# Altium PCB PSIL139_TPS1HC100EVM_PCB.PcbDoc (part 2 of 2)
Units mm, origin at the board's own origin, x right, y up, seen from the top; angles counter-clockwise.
Board outline 106.25 x 70 mm, 4 copper layers (Top Layer, Power, Ground, Bottom Layer), stack 1.565 mm thick; 66 components, 26 nets, 179 pads, 130 vias.
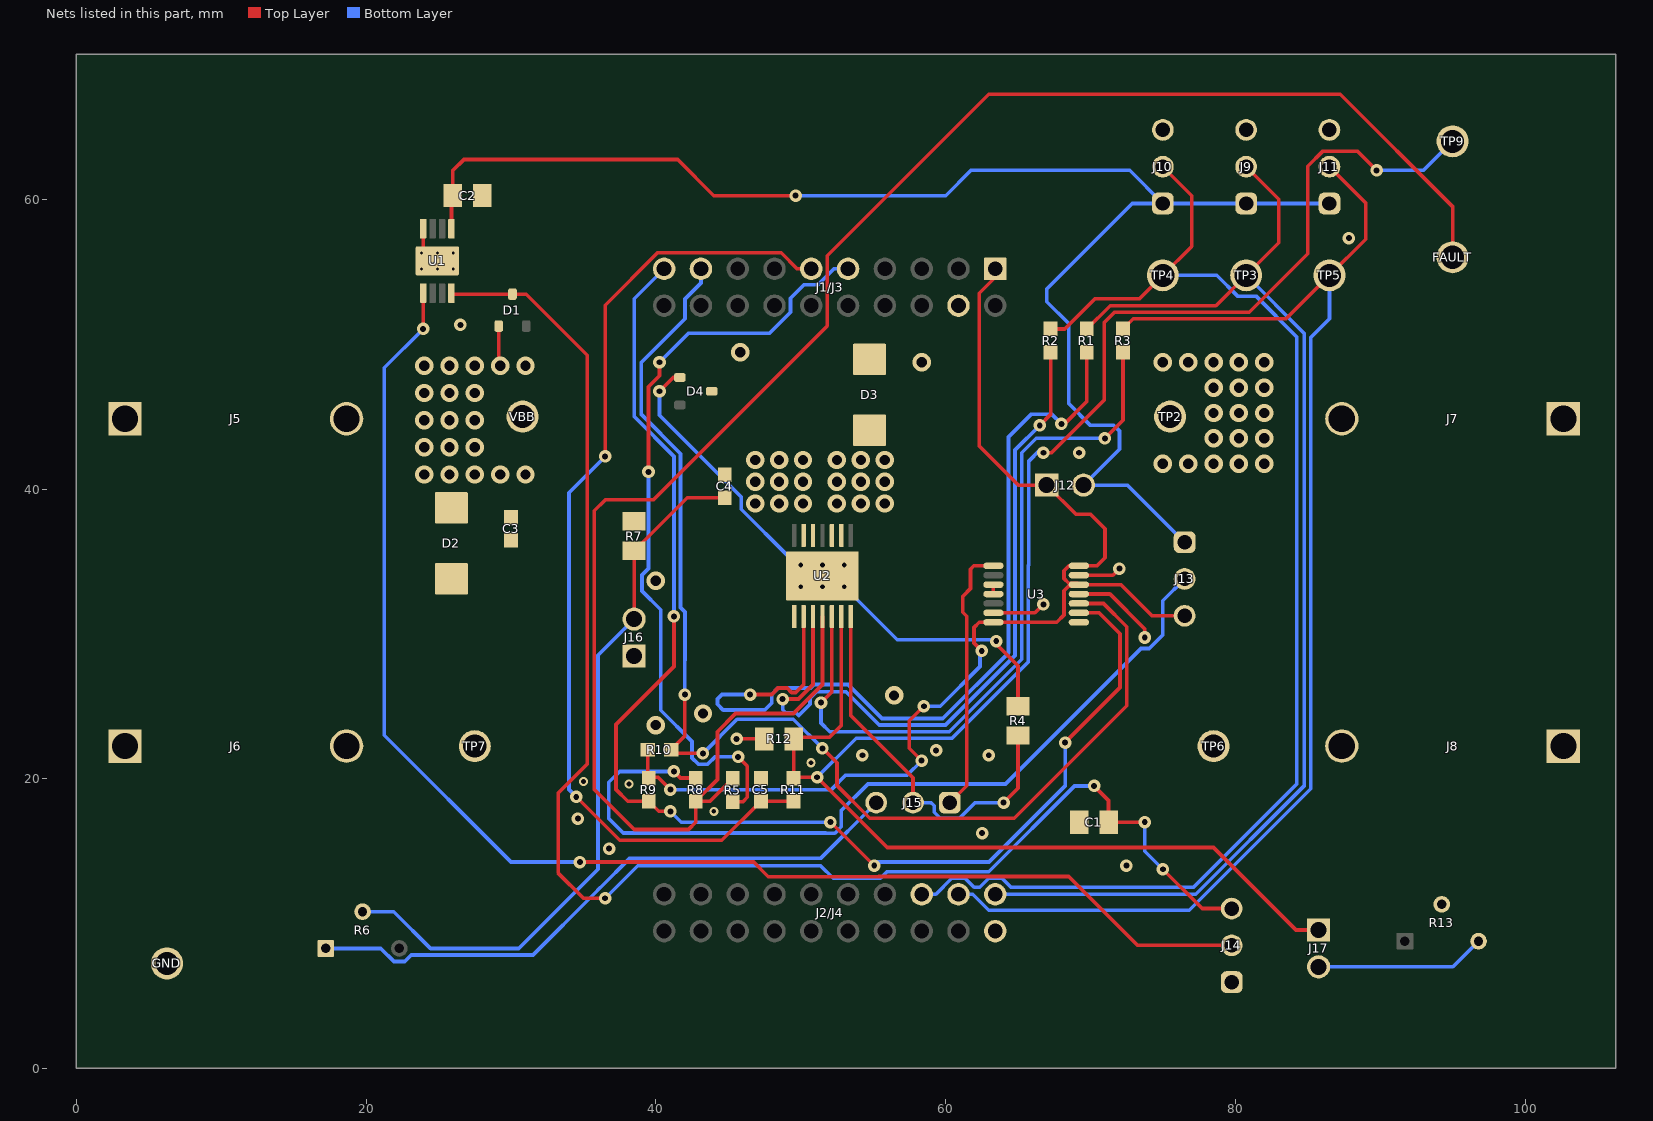
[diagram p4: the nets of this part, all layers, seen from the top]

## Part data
C1: library part CMP-0007980-2, "CAP, CERM, 1 uF, 100 V, +/- 10%, X7S, AEC-Q200 Grade 1, 0805", Cap_Case=0805, Manufacturer=TDK, Supplier Part Number 1=445-6974-1-ND, TempCo=X7S, Tolerance_%=10%, Value1="0.008255 ohm", Value2=100V, ValueDisplayed=1uF
C2: library part CMP-0007977-1, "CAP, CERM, 2.2 uF, 50 V, +/- 10%, X7R, AEC-Q200 Grade 1, 0805", Cap_Case=0805, Manufacturer=TDK, Supplier Part Number 1=445-174216-1-ND, TempCo=X7R, Tolerance_%=10%, Value1="0.003288 ohm", Value2=50V, ValueDisplayed=2.2uF
C3: library part CMP-0007103-2, "CAP, CERM, 0.22 uF, 25 V, +/- 10%, X8R, AEC-Q200 Grade 0, 0603", Cap_Case=0603, Manufacturer=TDK, Supplier Part Number 1=445-12597-1-ND, TempCo=X8R, Tolerance_%=10%, Value1=Unknown, Value2=25V, ValueDisplayed=0.22uF
C4: library part CMP-0007090-1, "CAP, CERM, 0.1 uF, 25 V, +/- 10%, X8R, AEC-Q200 Grade 0, 0603", Cap_Case=0603, Manufacturer=TDK, Supplier Part Number 1=445-5885-1-ND, TempCo=X8R, Tolerance_%=10%, Value1=Unknown, Value2=25V, ValueDisplayed=0.1uF
C5: library part CMP-0007130-1, "CAP, CERM, 100 pF, 100 V, +/- 5%, C0G/NP0, AEC-Q200 Grade 1, 0603", Cap_Case=0603, Manufacturer=MuRata, Supplier Part Number 1=490-4771-1-ND, TempCo=C0G/NP0, Tolerance_%=5%, Value1=Unknown, Value2=100V, ValueDisplayed=100pF
D1 D4: library part CMP-0076901-1, "Diode, Switching, 200 V, 0.2 A, SOT-23", Manufacturer="Diodes Inc.", Supplier Part Number 1=BAS21-FDICT-ND, Value1=0.2A, Value2=1.25V
D2 D3: library part CMP-0086728-1, "Diode TVS Single Bi-Dir 36V 600W 2-Pin SMB", Manufacturer=Littelfuse
FAULT TP3 TP4 TP5 TP9: library part CMP-0055158-1, "Test Point, Multipurpose, Green, TH", Color=Green, Manufacturer=Keystone, Supplier Part Number 1=36-5126-ND
GND TP6 TP7: library part CMP-0055148-1, "Test Point, Multipurpose, Black, TH", Color=Black, Manufacturer=Keystone, Supplier Part Number 1=36-5011-ND
J1/J3: library part CMP-0003837-4, "Receptacle, 2.54mm, 10x2, Tin, TH", Alternate Manufacturer="Major League Electronics", Alternate PartNumber=CRD-081413-A-G, Manufacturer=Samtec, Supplier Part Number 1=SAM1204-10-ND
J2/J4: library part CMP-0078266-2, "Receptacle, 2.54mm, 10x2, Tin, TH", Alternate Manufacturer="Major League Electronics", Alternate PartNumber=CRD-081413-A-G, Manufacturer=Samtec, Supplier Part Number 1=SAM1204-10-ND
J5 J7: library part CMP-0055393-2, "Standard Banana Jack, insulated, 10A, red", Manufacturer="DEM Manufacturing", Supplier Part Number 1=30M0087
J6 J8: library part CMP-0055389-3, "Standard Banana Jack, insulated, 10A, black", Manufacturer="DEM Manufacturing", Supplier Part Number 1=45M6896
J9 J10 J11 J13 J14 J15: library part CMP-0075356-1, "Header, 2.54mm, 3x1, Gold, TH", Color=Black, Current_A=2A, Manufacturer=3M, Supplier Part Number 1=961103-6804-AR-ND
J12 J16 J17: library part CMP-0075197-1, "Header, 2.54mm, 2x1, TH", Color=Black, Current_A=2A, Manufacturer=3M, Supplier Part Number 1=3M9447-ND, Voltage_V=1kV
Logo1: library part CMP-0074844-1
Logo2: library part CMP-0074838-1, "Texas Instrument Corporate Signature"
Logo3: library part CMP-0074847-1, "FCC_disclaimer"
Logo4: library part CMP-0074769-1
R1 R2 R3 R5 R11: library part CMP-0022458-4, "RES, 4.99 k, 1%, 0.1 W, AEC-Q200 Grade 0, 0603", Manufacturer=Vishay-Dale, Power_W=100mW, Supplier Part Number 1=541-4.99KHCT-ND, TempCo="100 ppm/C", Tolerance_%=1%, Value2=0.1W, Value_Code=4k99, ValueDisplayed=4.99k
R4: library part CMP-0021756-3, "RES, 59.0 k, 1%, 0.125 W, AEC-Q200 Grade 0, 0805", Manufacturer=Panasonic, Power_W=125mW, Supplier Part Number 1=P59.0KCCT-ND, TempCo="100 ppm/C", Tolerance_%=1%, Value2=0.125W, Value_Code=59k0, ValueDisplayed=59.0k
R6: library part CMP-0091455-1, "Res Cermet Trimmer 100K Ohm 10% 1/2W 1(Elec)/1(Mech)Turn 5mm (6.71 X 7.04 X 14.63mm) Pin Thru-Hole Tube", Digikey Part Number=3362P-1-104TLF-ND, Manufacturer=Bourns, Mouser Part Number=652-3362P-1-104TLF, Operating Temperature Range="-55°C to +125°C", Power_W=0.5W, TempCo=100ppm/°C, Tolerance_%=10%
R7: library part CMP-0020619-3, "RES, 1.0 k, 5%, 0.125 W, AEC-Q200 Grade 0, 0805", Manufacturer=Panasonic, Power_W=125mW, Supplier Part Number 1=P1.0KACT-ND, TempCo="200 ppm/C", Tolerance_%=5%, Value2=0.125W, Value_Code=1k00, ValueDisplayed=1.0k
R8 R9 R10: library part CMP-0086251-1, "RES, 10.0 k, 0.05%, 0.1 W, AEC-Q200 Grade 0, 0603", Manufacturer=Panasonic, Power_W=100mW, TempCo="10 ppm/C", Tolerance_%=0.05%, Value2=0.1W, Value_Code=10k0, ValueDisplayed=10.0k
R12: library part CMP-0021848-2, "RES, 1.00 k, 1%, 0.25 W, 0805", Manufacturer=Panasonic, Power_W=250mW, Supplier Part Number 1=P16058CT-ND, TempCo="100 ppm/C", Tolerance_%=1%, Value2=0.25W, Value_Code=1k00, ValueDisplayed=1.00k
R13: library part CMP-0091381-1, "1 kOhms 0.5W, 1/2W PC Pins Through Hole Trimmer Potentiometer Cermet 1 Turn Top Finger Adjustment", Digikey Part Number=3362P-1-102TLF-ND, Manufacturer=Bourns, Mouser Part Number=652-3362P-1-102TLF, Operating Temperature Range="-55°C to +125°C", Power_W=500mW, TempCo=100ppm/°C, Tolerance_%=10%
SH-J1 SH-J2 SH-J3 SH-J4 SH-J5 SH-J6 SH-J7 SH-J8 SH-J9: library part CMP-0003623-1, "Shunt, 100mil, Gold plated, Black", Alternate Manufacturer=3M, Alternate PartNumber=969102-0000-DA, Manufacturer=Samtec, Supplier Part Number 1=SNT-100-BK-G-ND
TP2 VBB: library part CMP-0055147-1, "Test Point, Multipurpose, Red, TH", Color=Red, Manufacturer=Keystone, Supplier Part Number 1=36-5010-ND
U1: library part CMP-0035936-2, "Single Output LDO, 100 mA, Fixed 3.3 V Output, 3 to 60 V Input, with Enable and Power Good, 8-pin MSOP (DGN), -40 to 125 degC, Green (RoHS & no Sb/Br)", Manufacturer="Texas Instruments", Power Good=TRUE, Rating=Catalog
U2: library part CMP-0091243-1, "100-mO Single-Channel Smart High-Side Power Switch, HTSSOP14", Manufacturer="Texas Instruments", Max Supply Voltage=28V, Min Supply Voltage=2.6V, Nominal Supply Current=3mA, Operating Temperature Range="-40°C to +150°C"
U3: library part CMP-0066591-1, "256-Taps Dual-Channel Digital Potentiometer With I2C Interface and Nonvolatile Memory, PW0014A (TSSOP-14)", Alternate Manufacturer="Texas Instruments"
ZZ1: library part CMP-0077236-1
ZZ2: library part CMP-0077237-1
ZZ3: library part CMP-0077238-1

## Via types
v1: diameter 1.27, hole 0.711, Top Layer to Bottom Layer, tented both sides, 62 vias
v2: diameter 0.864, hole 0.406, Top Layer to Bottom Layer, tented both sides, 52 vias
v3: diameter 0.63, hole 0.33, Top Layer to Bottom Layer, 6 vias
v4: diameter 0.5, hole 0.2, Top Layer to Bottom Layer, tented both sides, 4 vias
v5: diameter 0.63, hole 0.33, Top Layer to Bottom Layer, tented both sides, 4 vias
v6: diameter 0.5, hole 0.2, Top Layer to Bottom Layer, 2 vias

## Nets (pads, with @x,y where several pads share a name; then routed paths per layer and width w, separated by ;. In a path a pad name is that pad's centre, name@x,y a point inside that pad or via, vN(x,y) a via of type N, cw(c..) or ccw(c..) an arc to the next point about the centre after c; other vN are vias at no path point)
3V3LDO: C2.1 J9.1 J10.1 J11.1 J12.2 J13.1 U1.1 | length 104.2
  Top Layer w0.254: U1.1@25.886,57.975 25.886,60.155 C2.1@25.984,60.253 25.984,61.984 26.75,62.75 41.503,62.75 44,60.253 v2(49.651,60.253)
  Bottom Layer w0.254: v2(49.651,60.253) 60.003,60.253 61.75,62 72.71,62 J10.1@75,59.71 ; J13.1@76.5,36.33 72.562,40.268 J12.2@69.52,40.268 72,42.748 72,44 71.608,44.392 70.009,44.392 68.5,45.901 68.5,51.418 66.991,52.927 66.991,53.814 72.887,59.71 J10.1@75,59.71 ; J11.1@86.5,59.71 J9.1@80.75,59.71 J10.1@75,59.71
DIAG_EN_IC: J2/J4.38 J10.2 R2.1 TP4.1 | length 90.4
  Top Layer w0.254: R2.1@67.25,51.05 68.231,51.05 70.316,53.135 73.385,53.135 TP4.1@75,54.75 77,56.75 77,60.25 J10.2@75,62.25
  Bottom Layer w0.254: J2/J4.38@58.35,12.02 59.332,12.02 60.434,13.122 61.346,13.122 61.968,12.5 62.352,12.5 62.974,13.122 63.886,13.122 64.508,12.5 77.108,12.5 84.25,19.642 84.25,50.5 81.432,53.318 80.157,53.318 78.725,54.75 TP4.1@75,54.75
DIGIPOT_IN: J15.1 U3.1 | length 18.6
  Top Layer w0.254: J15.1@60.29,18.35 61.455,19.515 61.455,31.222 61.178,31.499 61.178,32.588 61.716,33.127 61.716,34.464 61.952,34.7 U3.1@63.3,34.7
DIGIPOT_SCL: J1/J3.9 R10.1 U3.10 | length 85.5
  Top Layer w0.254: v2(42,25.814) 42,22.95 R10.1@41.05,22 41.3,21.75 v2(43.25,21.75) ; v2(51.5,22.1) 52.5,21.1 52.5,19.537 54.764,17.273 64.741,17.273 72.5,25.032 72.5,30.5 70.9,32.1 U3.10@69.2,32.1
  Bottom Layer w0.254: v2(42,25.814) 42,28.179 42.009,28.187 42.009,31.514 41.704,31.819 41.704,42.438 39,45.142 39,48.75 42.008,51.758 42.008,53.116 43.11,54.218 J1/J3.9@43.11,55.2 ; v2(43.25,21.75) 45.608,24.108 49.492,24.108 v2(51.5,22.1)
DIGIPOT_SDA: J1/J3.10 R9.1 U3.9 | length 90.6
  Top Layer w0.254: v2(41,17.75) 40.2,17.75 R9.1@39.5,18.45 38.05,18.45 37.25,19.25 37.25,23.75 41.25,27.75 v2(41.25,31.2) ; v2(52.045,17) 52.077,17 v2(55.077,14) ; v2(68.25,22.5) 72.046,26.296 72.046,30 70.596,31.45 U3.9@69.2,31.45
  Bottom Layer w0.254: J1/J3.10@40.57,55.2 38.5,53.13 38.5,45 41.25,42.25 v2(41.25,31.2) ; v2(41,17.75) 41.75,17 v2(52.045,17) ; v2(55.077,14) 55.327,14.25 63,14.25 68.25,19.5 v2(68.25,22.5)
EN_IC: J2/J4.40 J9.2 R1.1 TP3.1 | length 83.2
  Top Layer w0.254: R1.1@69.75,51.05 71.36,52.66 78.66,52.66 TP3.1@80.75,54.75 83,57 83,60 J9.2@80.75,62.25
  Bottom Layer w0.254: J2/J4.40@63.43,12.02 77.27,12.02 84.75,19.5 84.75,50.75 TP3.1@80.75,54.75
FAULT_IC: FAULT.1 R5.1 R8.1 U2.4 | length 131.7
  Top Layer w0.254: R5.1@45.3,20.02 43.731,18.45 R8.1@42.75,18.45 ; U2.4@51.5,31.2 51.5,26.5 49.5,24.5 45.5,24.5 44.25,23.25 44.25,19.95 R8.1@42.75,18.45 ; FAULT.1@95,56 95,59.5 87.25,67.25 62.979,67.25 51.832,56.103 51.832,51.261 39.821,39.25 36.5,39.25 35.75,38.5 35.75,19.25 38.5,16.5 42.25,16.5 42.75,17 R8.1@42.75,18.45
GND: C1.2 C2.2 C3.2 C5.1 D2.2 D3.2 D4.3 GND.1 J1/J3.22 J2/J4.20 J6.1 J6.2 J8.1 J8.2 J9.3 J10.3 J11.3 J14.1 J16.1 R7.1 R12.2 R13.2 TP6.1 TP7.1 U1.4 U1.9@24.911,55.75 U3.6 U3.8 U3.11 U3.13 | length 16.5
  Top Layer w0.254: v4(23.811,56.3) 23.936,56.425 U1.4@23.936,57.975 ; v2(45.567,22.75) R12.2@47.484,22.75 ; U3.6@63.3,31.45 66.164,31.45 v2(66.75,32.036) ; U3.11@69.2,32.75 71.342,32.75 73.75,30.342 v2(73.75,29.75) ; U3.13@69.2,34.05 71.55,34.05 v2(72,34.5)
  other v1: 40,23.704 43.25,24.5 56.444,25.75 40,33.66 58.35,48.75 45.832,49.45
  other v2: 72.484,14 36.769,15.182 62.522,16.25 34.616,17.25 54.26,21.621 62.979,21.621 59.34,21.962 69.216,42.5 26.5,51.328 87.845,57.318
  other v4: 23.811,55.2 26.011,55.2 26.011,56.3
  other v5: 44,17.75 38.142,19.642 35,19.818 50.709,21.1
  other v6: 24.911,55.2 24.911,56.3
IC_GND: C4.2 D4.1 J16.2 R4.1 R6.2 R7.2 U2.1 U2.15 | length 85.6
  Top Layer w0.254: J16.2@38.5,31.02 R7.2@38.5,35.734 42.166,39.4 C4.2@44.75,39.4 ; v2(40.25,46.75) 41.2,47.7 D4.1@41.65,47.7 ; v2(63.5,29.5) 63.5,29.435 63.43,29.365 65,27.795 R4.1@65,25.016
  Bottom Layer w0.254: R6.2@19.75,10.825 21.91,10.825 24.45,8.285 30.535,8.285 36,13.75 36,28.52 J16.2@38.5,31.02 ; v2(40.25,46.75) 40.25,45.092 45.888,39.454 45.888,38.602 49.148,35.342 49.408,35.342 v3(50,34.75) ; v3(53,33.25) 56.663,29.587 63.413,29.587 v2(63.5,29.5)
  other v3: 50,33.25 51.5,33.25 51.5,34.75 53,34.75
LATCH_IC: J2/J4.39 J11.2 R3.1 TP5.1 | length 89.6
  Top Layer w0.254: R3.1@72.25,51.05 72.95,51.75 83.5,51.75 TP5.1@86.5,54.75 89,57.25 89,59.75 J11.2@86.5,62.25
  Bottom Layer w0.254: J2/J4.39@60.89,12.02 61.872,12.02 62.974,10.918 76.818,10.918 85.204,19.304 85.204,50.454 86.5,51.75 TP5.1@86.5,54.75
NetC1_1: C1.1 D1.3 J14.3 U1.8 | length 104.4
  Top Layer w0.254: U1.8@25.886,53.525 25.961,53.45 D1.3@30.1,53.45 31.05,53.45 35.269,49.231 35.269,21.019 33.25,19 33.25,13.5 35,11.75 v2(36.5,11.75) ; v2(70.25,19.5) 71.25,18.5 C1.1@71.25,17 v2(73.75,17) ; v2(75,13.75) 77.71,11.04 J14.3@79.75,11.04
  Bottom Layer w0.254: v2(36.5,11.75) 38.75,14 51.366,14 52.244,13.122 55.5,13.122 55.954,13.576 62.974,13.576 68.898,19.5 v2(70.25,19.5) ; v2(73.75,17) 73.75,15 v2(75,13.75)
NetJ1/J3_1: J1/J3.1 J12.1 J13.3 R9.2 R10.2 U3.7 U3.12 U3.14 | length 82.8
  Top Layer w0.254: R10.2@39.45,22 39.45,20.1 40.15,20.1 v2(41,19.25) ; v2(58.35,21.25) 57.5,22.1 57.5,24 v2(58.5,25) ; v2(62.5,28.828) 61.963,29.365 61.963,30.435 62.328,30.8 U3.7@63.3,30.8 67.673,30.8 68.173,31.3 68.173,32.979 68.496,33.302 69.102,33.302 U3.12@69.2,33.4 ; J1/J3.1@63.43,55.2 63.43,54.621 62.328,53.519 62.328,42.966 65.027,40.268 J12.1@66.98,40.268 68.998,38.25 70,38.25 71,37.25 71,35.25 70.45,34.7 U3.14@69.2,34.7 68.517,34.7 68.173,34.356 68.173,33.821 68.496,33.498 69.102,33.498 U3.12@69.2,33.4 ; J13.3@76.5,31.25 74.25,31.25 72.1,33.4 U3.12@69.2,33.4
  Bottom Layer w0.254: v2(41,19.25) 52.116,19.25 53.116,20.25 57.35,20.25 v2(58.35,21.25) ; v2(58.5,25) 59.631,25 62.381,27.75 62.381,28.709 v2(62.5,28.828)
NetJ1/J3_5: J1/J3.5 R5.2 | length 53.3
  Top Layer w0.254: v2(39.491,41.184) 39.491,47.064 40.25,47.823 v2(40.25,48.748) ; R5.2@45.3,18.42 46.013,18.42 46.31,18.717 46.31,20.871 v2(45.673,21.507)
  Bottom Layer w0.254: v2(39.491,41.184) 39.491,34.512 39.038,34.059 39.038,32.958 40.33,31.665 40.33,24.734 42.491,22.573 42.491,21.436 42.936,20.991 43.564,20.991 44.08,21.507 v2(45.673,21.507) ; v2(40.25,48.748) 42.252,50.75 47.838,50.75 49.292,52.204 49.292,53.172 50.218,54.098 51.186,54.098 52.288,55.2 J1/J3.5@53.27,55.2
NetJ13_2: J13.2 R8.2 | length 58.5
  Top Layer w0.254: v2(41.25,20.5) 41.7,20.05 R8.2@42.75,20.05
  Bottom Layer w0.254: v2(41.25,20.5) 37.5,20.5 36.75,19.75 36.75,17.25 37.75,16.25 51.722,16.25 51.73,16.241 52.359,16.241 52.803,16.686 52.803,17.803 54.642,19.642 64.142,19.642 73.491,28.991 74.064,28.991 75,29.927 75,32.29 J13.2@76.5,33.79
NetJ14_2: J14.2 U1.5 | length 96.2
  Top Layer w0.254: v2(23.936,51.05) U1.5@23.936,53.525 ; v2(34.75,14.25) 46.75,14.25 47.759,13.241 55.391,13.241 55.4,13.25 68.5,13.25 73.25,8.5 J14.2@79.75,8.5
  Bottom Layer w0.254: v2(23.936,51.05) 21.25,48.364 21.25,23 30,14.25 v2(34.75,14.25)
NetJ15_2: J15.2 R4.2 U2.7 | length 27.1
  Top Layer w0.254: U2.7@53.45,31.2 53.45,24.36 57.75,20.06 J15.2@57.75,18.35 ; v2(64,18.35) 65,19.35 R4.2@65,22.984
  Bottom Layer w0.254: J15.2@57.75,18.35 58.99,18.35 59.213,18.127 59.213,17.684 59.624,17.273 60.956,17.273 62.033,18.35 v2(64,18.35)
NetJ15_3: J15.3 R6.1 | length 42.9
  Bottom Layer w0.254: R6.1@17.21,8.285 21.014,8.285 21.916,7.383 22.664,7.383 23.112,7.831 31.513,7.831 35.741,12.059 35.741,12.064 36.186,12.509 36.191,12.509 38.182,14.5 51.36,14.5 J15.3@55.21,18.35
NetJ17_2: J17.2 R13.3 | length 11.8
  Bottom Layer w0.254: J17.2@85.75,7.015 95.02,7.015 R13.3@96.79,8.785
NetR1_2: R1.2 U2.2 | length 61.5
  Top Layer w0.254: v2(46.5,25.814) 47.991,25.814 48.436,26.259 49.064,26.259 49.369,25.954 49.654,25.954 50.2,26.5 U2.2@50.2,31.2 ; v2(68,44.5) 68.108,44.392 69.75,46.034 R1.2@69.75,49.45
  Bottom Layer w0.254: v2(46.5,25.814) 44.56,25.814 44.25,25.505 44.25,25.141 44.641,24.75 47.509,24.75 47.991,25.232 47.991,25.814 48.436,26.259 50.693,26.259 50.934,26.5 53.265,26.5 55.607,24.158 59.812,24.158 64.342,28.688 64.342,43.592 65.901,45.151 67.349,45.151 v2(68,44.5) 68.108,44.392 v2@68.108,44.25
NetR2_2: R2.2 U2.3 | length 50
  Top Layer w0.254: v2(48.75,25.5) 49.85,25.5 50.85,26.5 U2.3@50.85,31.2 ; v2(66.5,44.392) 67.25,45.142 R2.2@67.25,49.45
  Bottom Layer w0.254: v2(48.75,25.5) 48.75,24.763 48.951,24.562 49.68,24.562 49.871,24.371 50.641,25.141 50.641,25.564 51.085,26.009 51.714,26.009 51.723,26 53.123,26 55.419,23.704 60,23.704 64.796,28.5 64.796,42.688 v2(66.5,44.392)
NetR3_2: R3.2 U2.5 | length 50.7
  Top Layer w0.254: v2(51.4,25.25) 52.15,26.001 U2.5@52.15,31.2 ; v2(71,43.5) 72.25,44.75 R3.2@72.25,49.45
  Bottom Layer w0.254: v2(51.4,25.25) 51.4,23.851 52,23.25 60.25,23.25 65.25,28.25 65.25,42.5 66.25,43.5 v2(71,43.5)
NetU3_3: U3.3 U3.4 | length 0.7
  Top Layer w0.254: U3.4@63.3,32.75 U3.3@63.3,33.4
SNS_BP: C5.2 J1/J3.6 R11.1 | length 68.7
  Top Layer w0.254: v2(34.5,18.75) 37.5,15.75 44.55,15.75 C5.2@47.25,18.45 R11.1@49.5,18.45 ; v2(36.5,42.25) 36.5,52.688 40.114,56.302 48.646,56.302 49.748,55.2 J1/J3.6@50.73,55.2
  Bottom Layer w0.254: v2(34.5,18.75) 34,19.25 34,39.75 v2(36.5,42.25)
SNS_IC: J17.1 R11.2 R12.1 TP9.1 U2.6 | length 132.6
  Top Layer w0.254: R11.2@49.5,20.05 R11.2@49.516,20.066 ; U2.6@52.8,31.2 52.8,23.67 51.989,22.859 49.625,22.859 R12.1@49.516,22.75 R11.2@49.516,20.066 ; v2(66.75,42.5) 67.312,42.5 70.95,46.138 70.95,51.496 71.66,52.206 80.956,52.206 85,56.25 85,62.273 86.054,63.327 88.423,63.327 v2(89.75,62) ; J17.1@85.75,9.555 84.195,9.555 78.5,15.25 55.978,15.25 v2(51.128,20.1) 49.55,20.1 R11.2@49.516,20.066
  Bottom Layer w0.254: v2(51.128,20.1) 53.824,22.796 60.438,22.796 65.704,28.062 65.704,34.722 65.75,34.768 65.75,41.938 66.5,42.688 66.562,42.688 v2(66.75,42.5) ; v2(89.75,62) 93,62 TP9.1@95,64
VBB: C3.1 C4.1 D1.1 D2.1 J5.1 J5.2 U2.12 U2.13 VBB.1 | length 2.8
  Top Layer w0.254: D1.1@29.15,51.25 29.15,48.6 v1(29.25,48.5)
  other v1: 46.85,39 48.505,39 50.16,39 46.85,40.5 48.505,40.5 50.16,40.5 24,41 25.75,41 27.5,41 29.25,41 31,41 46.85,42 48.505,42 50.16,42 24,42.875 25.75,42.875 27.5,42.875 24,44.75 25.75,44.75 27.5,44.75 24,46.625 25.75,46.625 27.5,46.625 24,48.5 25.75,48.5 27.5,48.5 31,48.5
VOUT: D3.1 J7.1 J7.2 TP2.1 U2.9 U2.10
  other v1: 52.5,39 54.155,39 55.81,39 52.5,40.5 54.155,40.5 55.81,40.5 75,41.75 76.75,41.75 78.5,41.75 80.25,41.75 82,41.75 52.5,42 54.155,42 55.81,42 78.5,43.5 80.25,43.5 82,43.5 78.5,45.25 80.25,45.25 82,45.25 78.5,47 80.25,47 82,47 75,48.75 76.75,48.75 78.5,48.75 80.25,48.75 82,48.75
pads on no net: D1.2 D4.2 J1/J3.2 J1/J3.3 J1/J3.4 J1/J3.7 J1/J3.8 J1/J3.21 J1/J3.23 J1/J3.24 J1/J3.25 J1/J3.26 J1/J3.27 J1/J3.28 J1/J3.29 J1/J3.30 J2/J4.11 J2/J4.12 J2/J4.13 J2/J4.14 J2/J4.15 J2/J4.16 J2/J4.17 J2/J4.18 J2/J4.19 J2/J4.31 J2/J4.32 J2/J4.33 J2/J4.34 J2/J4.35 J2/J4.36 J2/J4.37 R6.3 R13.1 SH-J1.0 SH-J2.0 SH-J3.0 SH-J4.0 SH-J5.0 SH-J6.0 SH-J7.0 SH-J8.0 SH-J9.0 U1.2 U1.3 U1.6 U1.7 U1.9@24.911,55.75 U2.8 U2.11 U2.14 U3.2 U3.5
copper on no net: | length 1.6
  Top Layer w0.254: v2@61.75,32 62.594,32 62.596,32.002 63.202,32.002 63.3,32.1
  other v2: 62,32

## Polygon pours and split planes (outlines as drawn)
IC_GND on Top Layer "TOP_LAYER_IC_GND_P070" (solid, remove dead copper, pour order 70): 42.99,41 42.948,27.25 60.85,27.25 60.85,41
VBB on Top Layer "TOP_LAYER_VBB_P068" (solid, remove dead copper, pour order 68): 51,36 51,43.5 45.65,43.5 45.65,41.5 44.5,41.5 44.5,40.5 45.75,40.5 45.75,38 49.585,38 50,37.585 50,36
VOUT on Top Layer "TOP_LAYER_VOUT_P069" (solid, remove dead copper, pour order 69): 52,36 53,36 53,37.75 56.75,37.75 56.75,43 55.834,43 55.834,45.25 53.5,45.25 53.5,43.5 51.25,43.5 51.25,38.107 51.976,37.508
GND on Top Layer "TOP_LAYER_GND_P073" (solid, remove dead copper, pour order 73): 0,70 106,70 106.25,69.75 106.25,0 0.25,0 0,-0.25
VBB on Top Layer "TOP_LAYER_VBB_P072" (solid, remove dead copper, pour order 72): 1,49.75 33,49.75 33,37.5 24.25,37.5 22.25,39.75 1.257,40
VOUT on Top Layer "TOP_LAYER_VOUT_P071" (solid, remove dead copper, pour order 71): 105.75,50 73.5,50 73.5,40 105.75,40
VOUT on Power "POWER_VOUT_P075" (solid, remove dead copper, pour order 75): 51.5,69.353 51.5,0.647 51.603,0.75 106,0.75 106,68.75 105.25,69.5
VBB on Power "POWER_VBB_P074" (solid, remove dead copper, pour order 74): 0,69.75 0.25,70 51,70 51,0.25 51.25,0 0,0
GND on Bottom Layer "BOTTOM_LAYER_GND_P078" (solid, remove dead copper, pour order 78): 0.5,69.75 0.25,69.5 0.25,0 105.75,0 106,0.25 105.75,0.5 105.75,69.75
IC_GND on Bottom Layer "BOTTOM_LAYER_IC_GND_P077" (solid, remove dead copper, pour order 77): 42.57,42.5 42.57,27 60.75,27 60.75,42.5
GND on Ground "GROUND_GND_P076" (solid, remove dead copper, pour order 76): 0.25,70 106.25,70 106.25,0.25 0.25,0.25

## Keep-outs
Keep-Out Layer:
  text ".Layer_Name" at 14.656,-21.806 h1.52

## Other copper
Top Layer:
  text ".Layer_Name" at 14.656,-21.806 h1.52
Bottom Layer:
  text ".Layer_Name" at 14.656,-21.806 h1.52

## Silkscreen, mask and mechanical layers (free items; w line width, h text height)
Top Overlay:
  text "DIAG_EN" at 73,67.25 h1.2
  text "EN" at 80.093,67.263 h1.2
  text "LATCH" at 85,67.25 h1.2
  text "PSIL139 A2" at 2,67 h1.85
  text "SNS" at 93.75,67 h1.5
  text "GND" at 70.045,64.5 h1.2
  text "3V3 LDO" at 68,59.25 h1.2
  text "SDA" at 40.57,56.75 h0.6 r45
  text "SCL" at 43.11,56.75 h0.6 r45
  text "SNS" at 50.73,56.75 h0.6 r45
  text "FAULT" at 53.25,56.75 h0.6 r45
  text "VOUT" at 68,45 h2
  text "LDO to BP / Power" at 58.35,39.2 h1.2
  text "LDO" at 78.5,35.931 h1.5
  text "BP" at 78.5,30.5 h1.5
  text "Fault Pull-Up" at 73.5,28 h1.5
  text "(ILIM)" at 64.718,26.669 h1
  text "GND Net / Bypass" at 35,24 h1.2
  text "(SNS)" at 52.643,22.859 h1
  text "GND" at 30.5,21.75 h1.85
  text "GND" at 71.75,21.75 h1.9
  text "DIGI POT" at 60.25,20.114 h1 r45
  text "POT" at 55,20.1 h1 r45
  text "Current Limit / Setting" at 52.964,14 h1
  text "EN" at 52.99,13.561 h0.6 r45
  text "DIAG_EN" at 47.948,13.442 h0.6 r45
  text "LATCH" at 50.488,13.442 h0.7 r45
  text "LDO EN" at 73.25,10.75 h1.2
  text "LDO DIS" at 73.25,5.5 h1.2
  text "TPS1HC100EVM" at 41,3.75 h2.75
  text "SNS Pot  / Enable" at 82.5,2.5 h1
  text "Current Limit" at 15.5,2 h1.85
  text "SNS" at 90.25,2 h1.85
  text ".Layer_Name" at 14.656,-21.806 h1.52
Bottom Overlay:
  text ".Layer_Name" at 14.656,-21.806 h1.52
Top Paste:
  text ".Layer_Name" at 14.656,-21.806 h1.52
Bottom Paste:
  text ".Layer_Name" at 14.656,-21.806 h1.52
Top Solder:
  text ".Layer_Name" at 14.656,-21.806 h1.52
  text ".Layer_Name" at 14.656,-21.806 h1.52
Bottom Solder:
  text ".Layer_Name" at 14.656,-21.806 h1.52
Drill Guide:
  text ".Layer_Name" at 14.656,-21.806 h1.52
M1 Board Outline:
  lines w0.254: -12.5,-0.32 106.25,0 106.25,69.18 ; 0,1.75 0,70 106.25,70
  text ".Layer_Name" at 14.656,-21.806 h1.52
M2 Board Dimensions:
  rectangle: 0,-6.985 3.175,-3.81
  rectangle: 3.175,-10.16 12.7,-6.985
  lines w0.178: 0,-6.985 25.4,-6.985 ; 3.175,-10.16 3.175,-3.81 ; 6.35,-10.16 6.35,-3.81 ; 12.7,-10.16 12.7,-3.81 ; 19.05,-10.16 19.05,-3.81 ; 0,-10.16 25.4,-10.16 25.4,-3.81 0,-3.81 0,-10.16
  text ".Layer_Name" at 14.656,-21.806 h1.52
M3 3D STEP Top:
  text ".Layer_Name" at 14.656,-21.806 h1.52
M4 3D STEP Bottom:
  text ".Layer_Name" at 14.656,-21.806 h1.52
M5 Assembly Top:
  lines w0.254: -7.417,-23.626 160.223,-23.626 ; -7.417,-18.462 160.274,-18.462 ; -7.417,-13.297 -7.417,-28.791 94.31,-28.791 160.274,-28.791 160.274,-13.297 -7.404,-13.297 -7.404,-28.791 32.614,-28.791 ; 55.194,-28.791 55.194,-13.297 ; 87.376,-18.462 87.376,-13.297 ; 108.712,-18.462 108.712,-13.297 ; 124.511,-28.956 124.511,-23.804
  text "COMPONENTS MARKED 'DNP' SHOULD NOT BE POPULATED." at 29.299,-8.09 h1.52
  text "ASSEMBLY VARIANT:" at 29.286,-11.024 h1.52
  text ".VariantName" at 55.601,-11.024 h1.52
  text "PCB VIEWED FROM TOP SIDE" at -5.804,-16.654 h1.52
  text "BOARD #:" at 57.099,-16.654 h1.52
  text ".PRJ_Number" at 70.955,-16.654 h1.52
  text "REV:" at 92.405,-16.654 h1.52
  text ".PCB_Rev" at 99.809,-16.654 h1.52
  text "SVN REV:" at 113.69,-16.654 h1.52
  text ".VersionControl_RevNumber" at 126.543,-16.654 h1.52
  text "TID #:" at 57.099,-21.819 h1.52
  text ".TID" at 70.955,-21.819 h1.52
  text "PLOT NAME =" at -5.804,-27.034 h1.52
  text ".plot_File_Name" at 14.656,-27.034 h1.52
  text "GENERATED    :" at 57.15,-27.034 h1.52
  text ".Print_Date" at 79.235,-27.034 h1.52
  text ".Print_Time" at 97.752,-27.034 h1.52
  text "TEXAS INSTRUMENTS" at 129.87,-27.034 h1.52
M6 Assembly Bottom:
  lines w0.254: -7.429,-18.474 160.261,-18.474 ; -7.379,-23.639 160.261,-23.639 ; 28.334,-28.969 28.334,-23.817 ; 44.133,-18.474 44.133,-13.31 ; 65.468,-18.474 65.468,-13.31 ; 97.65,-28.804 97.65,-13.31 ; 120.231,-28.804 160.249,-28.804 160.249,-13.31 -7.429,-13.31 -7.429,-28.804 58.534,-28.804 160.261,-28.804 160.261,-13.31
  text "COMPONENTS MARKED 'DNP' SHOULD NOT BE POPULATED." at 154.991,-8.077 h1.52
  text ".VariantName" at 128.473,-11.024 h1.52
  text "ASSEMBLY VARIANT:" at 154.864,-11.024 h1.52
  text ".VersionControl_RevNumber" at 26.302,-16.667 h1.52
  text "SVN REV:" at 39.154,-16.667 h1.52
  text ".PCB_Rev" at 53.035,-16.667 h1.52
  text "REV:" at 60.439,-16.667 h1.52
  text ".PRJ_Number" at 81.89,-16.667 h1.52
  text "BOARD #:" at 95.745,-16.667 h1.52
  text "PCB VIEWED FROM BOTTOM SIDE" at 158.648,-16.667 h1.52
  text ".TID" at 81.89,-21.831 h1.52
  text "TID #:" at 95.745,-21.831 h1.52
  text "TEXAS INSTRUMENTS" at 22.974,-27.047 h1.52
  text ".Print_Time" at 55.093,-27.047 h1.52
  text ".Print_Date" at 73.609,-27.047 h1.52
  text "GENERATED    :" at 95.694,-27.047 h1.52
  text ".plot_File_Name" at 138.189,-27.047 h1.52
  text "PLOT NAME =" at 158.648,-27.047 h1.52
M8 LPKF Text Bottom:
  text "String" at -9.75,50.5 h1.85
M9 Title Sheet:
  drawing of 57 lines, arcs and shapes, not listed
  text "1" at 18.792,204.127 h1.78
  text "2" at 82.182,204.127 h1.78
  text "3" at 145.411,204.127 h1.78
  text "4" at 209.08,204.127 h1.78
  text "5" at 272.555,204.127 h1.78
  text "6" at 336.182,204.127 h1.78
  text "A" at -10.579,175.095 h1.78
  text "A" at 365.341,175.095 h1.78
  text "B" at -10.579,114.643 h1.78
  text "B" at 365.341,114.643 h1.78
  text "C" at -10.579,54.318 h1.78
  text "C" at 365.341,54.318 h1.78
  text "PROJECT TITLE:" at 288.125,7.048 h1.14
  text ".PRJ_Title" at 289.395,3.662 h1.78
  text "DESIGNED FOR:" at 288.125,-0.597 h1.14
  text ".PRJ_Customer" at 289.395,-4.153 h1.78
  text "D" at -10.579,-5.88 h1.78
  text "D" at 365.341,-5.88 h1.78
  text "FILE NAME:" at 288.125,-8.217 h1.14
  text ".PCB_File_Name_No_Path" at 289.395,-11.265 h1.78
  text "Texas Instruments (TI) and/or its licensors do not warrant the accuracy or completeness of this specification" at 161.9,-15.376 h1.14
  text "ENGINEER:" at 288.125,-15.583 h1.14
  text "LAYOUT BY:" at 326.352,-15.583 h1.14
  text "or any information contained therein. TI and/or its licensors do not warrant that this design will meet" at 160.757,-18.237 h1.14
  text ".PRJ_Engineer" at 289.395,-19.52 h1.78
  text ".PCB_Layout" at 327.635,-19.52 h1.78
  text "the specifications, will be suitable for your application or fit for any particular purpose, or will operate in" at 160.757,-21.099 h1.14
  text ".Layer_Name" at 14.656,-21.806 h1.52
  text "ALTIUM DESIGNER VERSION:" at 326.352,-23.457 h1.14
  text "an implementation. TI and/or its licensors do not warrant that the design is production worthy. You should" at 160.757,-23.961 h1.14
  text "completely validate and test your design implementation to confirm the system functionality for your application." at 161.9,-26.822 h1.14
  text ".print_Scale" at 289.395,-26.843 h1.78
  text ".Application_BuildNumber" at 327.635,-26.843 h1.78
  text "1" at 18.792,-32.093 h1.78
  text "2" at 82.182,-32.093 h1.78
  text "3" at 145.411,-32.093 h1.78
  text "4" at 209.08,-32.093 h1.78
  text "5" at 272.555,-32.093 h1.78
  text "6" at 336.182,-32.093 h1.78
M10 Fab Notes:
  drawing of 189 lines, arcs and shapes, not listed
  text "DESIGN INFORMATION" at 314.503,161.447 h1.52
  text "MIN. TRACK WIDTH:" at 298.131,158.091 h1.52
  text "8" at 325.976,158.091 h1.52
  text "MIL" at 329.907,158.091 h1.52
  text "MIN. CLEARANCE:" at 298.131,154.938 h1.52
  text "7" at 324.452,154.938 h1.52
  text "MIL" at 329.907,154.938 h1.52
  text "MIN. VIA PAD SIZE:" at 298.131,151.785 h1.52
  text "24" at 325.214,151.785 h1.52
  text "MIL" at 329.907,151.785 h1.52
  text "0.05mm (2MIL)" at 315.784,148.486 h1.52
  text "MINIMUM ANNULAR RING" at 289.769,148.277 h1.52
  text "EXTERNAL" at 333.768,148.277 h1.52
  text "PER" at 294.849,145.48 h1.52
  text "IPC-D-275 CLASS 2 LEVEL C" at 300.437,145.48 h1.52
  text "MIL, HOLES" at 338.238,142.928 h1.52
  text "+/-" at 328.27,142.709 h1.52
  text "+/-" at 349.961,142.709 h1.52
  text "REGISTRATION TOLERANCES:" at 289.769,142.682 h1.52
  text "METAL" at 320.243,142.682 h1.52
  text "5" at 334.879,142.683 h1.52
  text "3" at 356.037,142.683 h1.52
  text "MIL" at 358.99,142.682 h1.52
  text "HOLE SIZE TOLERANCE (UNLESS OTHERWISE SPECIFIED):" at 289.769,140.185 h1.52
  text "+/-" at 349.961,140.112 h1.52
  text "3" at 356.037,140.085 h1.52
  text "MIL" at 358.99,140.085 h1.52
  text "MATERIAL:" at 287.87,136.589 h1.52
  text "FR-4 High Tg" at 312.926,133.324 h1.52
  text "X" at 309.257,133.122 h1.52
  text "FR-408" at 298.563,133.007 h1.52
  text "OTHER" at 336.358,133.007 h1.52
  text "62 MIL (1.6mm) +/-10%" at 306.694,129.374 h1.52
  text "X" at 303.643,129.312 h1.52
  text "THICKNESS:" at 289.769,129.165 h1.52
  text "OTHER" at 339.33,129.165 h1.52
  text "TOLERANCE:" at 289.769,125.652 h1.52
  text "X" at 311.314,125.652 h1.52
  text "ANSI IPC-6012 TYPE 3 CLASS 2" at 315.836,125.652 h1.52
  text "OTHER +/-" at 315.835,121.989 h1.52
  text "BOW & TWIST:" at 289.769,118.302 h1.52
  text "X" at 311.314,118.302 h1.52
  text "ANSI IPC-6012 TYPE 3 CLASS 2" at 315.836,118.302 h1.52
  text "OTHER +/-" at 315.835,114.576 h1.52
  text "DRILLING:" at 287.87,111.258 h1.52
  text "NC_DRILL FILES" at 332.599,108.586 h1.52
  text "REFERENCE:" at 289.769,108.486 h1.52
  text "X" at 306.463,108.484 h1.52
  text "AS SHOWN" at 310.984,108.486 h1.52
  text "X" at 329.348,108.486 h1.52
  text "OTHER" at 340.168,104.873 h1.52
  text "PTH COPPER THICKNESS:" at 289.761,104.783 h1.52
  text "X" at 318.697,104.783 h1.52
  text "20-30 um" at 321.948,104.783 h1.52
  text "BOARD FINISH:" at 287.87,101.034 h1.52
  text "SILKSCREEN:" at 291.812,98.237 h1.52
  text "X" at 316.14,98.237 h1.52
  text "TOP" at 319.112,98.237 h1.52
  text "X" at 329.094,98.237 h1.52
  text "BOTTOM" at 332.091,98.237 h1.52
  text "SILKSCREEN COLOR:" at 291.812,94.295 h1.52
  text "X" at 316.115,94.295 h1.52
  text "WHITE" at 319.112,94.295 h1.52
  text "OTHER" at 332.091,94.295 h1.52
  text "X" at 319.442,90.734 h1.52
  text "GREEN" at 322.439,90.652 h1.52
  text "OTHER" at 338.136,90.652 h1.52
  text "SOLDER RESIST COLOR:" at 291.812,90.477 h1.52
  text "X" at 334.5,87 h1.52
  text "MATTE" at 322.439,86.734 h1.52
  text "SEMI-GLOSS" at 338.125,86.717 h1.52
  text "IMMERSION GOLD (ENIG)" at 314.819,82.345 h1.52
  text "ENEPIG" at 348.793,82.162 h1.52
  text "SURFACE FINISH:" at 287.87,82.136 h1.52
  text "X" at 310.298,82.136 h1.52
  text "IMM. TIN/SILVER OR EQUIV" at 296.24,78.649 h1.52
  text "OTHER" at 332.599,78.549 h1.52
  text "ARRAY/PANEL:" at 287.87,74.602 h1.52
  text "CUT AND TRIM PER M1 BOARD OUTLINE" at 314.819,74.393 h1.52
  text "N.C. ROUTE" at 314.819,70.94 h1.52
  text "X" at 332.295,70.94 h1.52
  text "V. SCORE" at 336.816,70.94 h1.52
  text "CERTIFICATION:" at 287.87,67.66 h1.52
  text "MATERIALS AND WORKMANSHIP FOR ALL PCBS" at 306.285,67.66 h1.52
  text "TO MEET OR EXCEED THE REQUIREMENTS OF:" at 306.285,65.271 h1.52
  text "X" at 297.078,62.003 h1.52
  text "ANSI IPC-A-600F CLASS ->" at 300.329,62.003 h1.52
  text "X" at 342.188,62.003 h1.52
  text "2" at 344.982,62.003 h1.52
  text "1" at 336.981,61.965 h1.52
  text "3" at 353.973,61.965 h1.52
  text "X" at 317.702,58.252 h1.52
  text "RoHS" at 320.953,58.252 h1.52
  text "OTHER" at 337.321,58.252 h1.52
  text "PER ORDER" at 347.407,58.252 h1.52
  text "ALL BOARDS MUST MEET OR EXCEED UL94-V0 REQUIREMENTS." at 288.569,54.345 h1.52
  text "PCB MUST BEAR THE UL94V-0 UL REGISTERED MATERIAL ID NUMBER" at 288.569,51.397 h1.52
  text "ADDITIONAL REQUIREMENTS:" at 287.87,47.094 h1.52
  text "MICROSECTION:" at 289.769,44.373 h1.52
  text "YES" at 312.775,44.373 h1.52
  text "REQUIRED" at 334.657,40.707 h1.52
  text "BARE BOARD ELEC. TEST:" at 289.769,40.634 h1.52
  text "NONE" at 322.935,40.634 h1.52
  text "X" at 331.66,40.634 h1.52
  text "PER ORDER" at 349.693,40.634 h1.52
  text "XX MIL VIAS REQUIRE NON-CONDUCTIVE FILL AND PLANARIZE" at 294.04,35.428 h1.5
  text "XX MIL VIAS REQUIRE CONDUCTIVE FILL AND PLANARIZE" at 294.243,32.787 h1.52
  text "OUTER XX MIL TRACES REQUIRE 50 OHM SINGLE-ENDED IMPEDANCE" at 294.218,28.637 h1.47
  text "LAYER 2 & 3 (INNER LAYERS) XX MIL WIDE, XX MIL SPACE / TRACES REQUIRE 100 OHM DIFFERENTIAL IMPEDANCE" at 294.015,22.65 h1.52
  text ".Layer_Name" at 14.656,-21.806 h1.52
M11 Gerber Information:
  lines w0.254: -7.417,-23.626 160.223,-23.626 ; -7.417,-18.462 160.274,-18.462 ; -7.417,-13.297 -7.417,-28.791 94.31,-28.791 160.274,-28.791 160.274,-13.297 -7.404,-13.297 -7.404,-28.791 32.614,-28.791 ; 55.194,-28.791 55.194,-13.297 ; 87.376,-18.462 87.376,-13.297 ; 108.712,-18.462 108.712,-13.297 ; 124.511,-28.956 124.511,-23.804
  text "ALL ARTWORK VIEWED FROM TOP SIDE" at -5.804,-16.654 h1.52
  text "BOARD #:" at 57.099,-16.654 h1.52
  text ".PRJ_Number" at 70.955,-16.654 h1.52
  text "REV:" at 92.405,-16.654 h1.52
  text ".PCB_Rev" at 99.809,-16.654 h1.52
  text "SVN REV:" at 113.69,-16.654 h1.52
  text ".VersionControl_RevNumber" at 126.543,-16.654 h1.52
  text "LAYER NAME =" at -5.804,-21.806 h1.52
  text "TID #:" at 57.099,-21.819 h1.52
  text ".TID" at 70.955,-21.819 h1.52
  text "PLOT NAME =" at -5.804,-27.034 h1.52
  text ".plot_File_Name" at 14.656,-27.034 h1.52
  text "GENERATED    :" at 57.15,-27.034 h1.52
  text ".Print_Date" at 79.235,-27.034 h1.52
  text ".Print_Time" at 97.752,-27.034 h1.52
  text "TEXAS INSTRUMENTS" at 129.87,-27.034 h1.52
M12 Stackup:
  drawing of 295 lines, arcs and shapes, not listed
  text "Layer" at 161.862,168.035 h1.52
  text "Name" at 172.274,168.035 h1.52
  text "Material" at 195.89,168.035 h1.52
  text "Thickness" at 217.728,168.035 h1.52
  text "Constant" at 234.233,168.035 h1.52
  text "Board Layer Stack" at 248.708,168.035 h1.52
  text "1" at 161.862,164.987 h1.52
  text "Top Overlay" at 172.274,164.987 h1.52
  text "2" at 161.862,161.939 h1.52
  text "Top Solder" at 172.274,161.939 h1.52
  text "Solder Resist" at 195.89,161.939 h1.52
  text "0.40mil" at 217.728,161.939 h1.52
  text "3.5" at 234.233,161.939 h1.52
  text "3" at 161.862,158.891 h1.52
  text "Top Layer" at 172.274,158.891 h1.52
  text "Copper" at 195.89,158.891 h1.52
  text "1.40mil" at 217.728,158.891 h1.52
  text "4" at 161.862,155.843 h1.52
  text "Dielectric 1" at 172.274,155.843 h1.52
  text "8.00mil" at 217.728,155.843 h1.52
  text "4.2" at 234.233,155.843 h1.52
  text "5" at 161.862,152.795 h1.52
  text "Power" at 172.274,152.795 h1.52
  text "Copper" at 195.89,152.795 h1.52
  text "1.40mil" at 217.728,152.795 h1.52
  text "6" at 161.862,149.747 h1.52
  text "Dielectric 2" at 172.274,149.747 h1.52
  text "FR-4" at 195.89,149.747 h1.52
  text "40.00mil" at 217.728,149.747 h1.52
  text "4.8" at 234.233,149.747 h1.52
  text "7" at 161.862,146.699 h1.52
  text "Ground" at 172.274,146.699 h1.52
  text "Copper" at 195.89,146.699 h1.52
  text "1.40mil" at 217.728,146.699 h1.52
  text "8" at 161.862,143.651 h1.52
  text "Dielectric 3" at 172.274,143.651 h1.52
  text "8.00mil" at 217.728,143.651 h1.52
  text "4.2" at 234.233,143.651 h1.52
  text "9" at 161.862,140.603 h1.52
  text "Bottom Layer" at 172.274,140.603 h1.52
  text "Copper" at 195.89,140.603 h1.52
  text "1.40mil" at 217.728,140.603 h1.52
  text "10" at 161.862,137.555 h1.52
  text "Bottom Solder" at 172.274,137.555 h1.52
  text "Solder Resist" at 195.89,137.555 h1.52
  text "0.40mil" at 217.728,137.555 h1.52
  text "3.5" at 234.233,137.555 h1.52
  text "11" at 161.862,134.507 h1.52
  text "Bottom Overlay" at 172.274,134.507 h1.52
  text ".Layer_Name" at 14.656,-21.806 h1.52
M13 Component Bodies Top:
  text ".Layer_Name" at 14.656,-21.806 h1.52
M14 Component Bodies Bottom:
  text ".Layer_Name" at 14.656,-21.806 h1.52
M15 Courtyards Top:
  text ".Layer_Name" at 14.656,-21.806 h1.52
M16 Courtyards Bottom:
  text ".Layer_Name" at 14.656,-21.806 h1.52
Drill Drawing:
  circle w0.254: c136.234,78.248 r0.42
  circle w0.254: c136.234,78.248 r0.7
  circle w0.254: c136.234,75.098 r0.7
  lines w0.254: 135.534,58.646 136.934,58.646 136.934,60.047 135.534,60.047 135.534,58.646 ; 135.534,63.197 136.934,63.197 136.234,61.797 135.534,63.197 ; 135.534,65.297 135.884,65.297 135.884,64.947 136.584,64.947 136.584,65.297 136.934,65.297 136.934,65.997 136.584,65.997 136.584,66.347 135.884,66.347 135.884,65.997 135.534,65.997 135.534,65.297 ; 135.534,68.097 135.534,68.447 135.884,68.797 135.534,69.147 135.534,69.497 135.884,69.497 136.234,69.147 136.584,69.497 136.934,69.497 136.934,69.147 136.584,68.797 136.934,68.447 136.934,68.097 136.584,68.097 136.234,68.447 135.884,68.097 135.534,68.097 ; 135.534,71.598 135.884,71.598 136.234,71.248 136.584,71.598 136.934,71.598 136.584,71.948 136.934,72.298 136.584,72.298 136.234,72.648 135.884,72.298 135.534,72.298 135.884,71.948 135.534,71.598 ; 135.534,80.698 136.234,81.048 136.934,80.698 136.584,81.398 136.934,82.098 136.234,81.748 135.534,82.098 135.884,81.398 135.534,80.698 ; 135.534,83.849 136.934,83.849 136.934,85.249 135.534,85.249 135.534,83.849 ; 135.534,87.699 136.234,86.999 136.934,87.699 136.234,88.399 135.534,87.699 ; 135.814,84.129 136.654,84.129 136.654,84.969 135.814,84.969 135.814,84.129
  lines w0.305: 134.264,57.701 216.225,57.701 ; 134.264,89.204 216.225,89.204 ; 142.833,54.551 142.833,92.354 ; 151.258,54.551 151.258,92.354 ; 167.409,54.551 167.409,92.354 ; 173.983,54.551 173.983,92.354 ; 183.501,54.551 183.501,92.354 ; 201.854,54.551 201.854,92.354 ; 134.264,54.551 216.225,54.551 216.225,92.354 134.264,92.354 134.264,54.551
  text "Symbol" at 136.155,90.149 h1.83
  text "Quantity" at 143.779,90.149 h1.83
  text "Finished Hole Size" at 152.204,90.149 h1.83
  text "Plated" at 168.354,90.149 h1.83
  text "Hole Type" at 174.928,90.149 h1.83
  text "Drill Layer Pair" at 184.446,90.149 h1.83
  text "Hole Tolerance" at 202.799,90.149 h1.83
  text "6" at 143.779,86.999 h1.52
  text "7.87mil (0.200mm)" at 152.204,86.999 h1.52
  text "PTH" at 168.354,86.999 h1.52
  text "Round" at 174.928,86.999 h1.52
  text "Top Layer - Bottom Layer" at 184.446,86.999 h1.52
  text "10" at 143.779,83.849 h1.52
  text "12.99mil (0.330mm)" at 152.204,83.849 h1.52
  text "PTH" at 168.354,83.849 h1.52
  text "Round" at 174.928,83.849 h1.52
  text "Top Layer - Bottom Layer" at 184.446,83.849 h1.52
  text "52" at 143.779,80.698 h1.52
  text "16.00mil (0.406mm)" at 152.204,80.698 h1.52
  text "PTH" at 168.354,80.698 h1.52
  text "Round" at 174.928,80.698 h1.52
  text "Top Layer - Bottom Layer" at 184.446,80.698 h1.52
  text "6" at 143.779,77.548 h1.52
  text "25.59mil (0.650mm)" at 152.204,77.548 h1.52
  text "PTH" at 168.354,77.548 h1.52
  text "Round" at 174.928,77.548 h1.52
  text "Top Layer - Bottom Layer" at 184.446,77.548 h1.52
  text "62" at 143.779,74.398 h1.52
  text "28.00mil (0.711mm)" at 152.204,74.398 h1.52
  text "PTH" at 168.354,74.398 h1.52
  text "Round" at 174.928,74.398 h1.52
  text "Top Layer - Bottom Layer" at 184.446,74.398 h1.52
  text "18" at 143.779,71.248 h1.52
  text "39.37mil (1.000mm)" at 152.204,71.248 h1.52
  text "PTH" at 168.354,71.248 h1.52
  text "Round" at 174.928,71.248 h1.52
  text "Top Layer - Bottom Layer" at 184.446,71.248 h1.52
  text "+3.94mil/-1.97mil" at 202.799,71.248 h1.52
  text "40" at 143.779,68.097 h1.52
  text "40.16mil (1.020mm)" at 152.204,68.097 h1.52
  text "PTH" at 168.354,68.097 h1.52
  text "Round" at 174.928,68.097 h1.52
  text "Top Layer - Bottom Layer" at 184.446,68.097 h1.52
  text "6" at 143.779,64.947 h1.52
  text "43.31mil (1.100mm)" at 152.204,64.947 h1.52
  text "PTH" at 168.354,64.947 h1.52
  text "Round" at 174.928,64.947 h1.52
  text "Top Layer - Bottom Layer" at 184.446,64.947 h1.52
  text "10" at 143.779,61.797 h1.52
  text "63.00mil (1.600mm)" at 152.204,61.797 h1.52
  text "PTH" at 168.354,61.797 h1.52
  text "Round" at 174.928,61.797 h1.52
  text "Top Layer - Bottom Layer" at 184.446,61.797 h1.52
  text "8" at 143.779,58.646 h1.52
  text "70.87mil (1.800mm)" at 152.204,58.646 h1.52
  text "PTH" at 168.354,58.646 h1.52
  text "Round" at 174.928,58.646 h1.52
  text "Top Layer - Bottom Layer" at 184.446,58.646 h1.52
  text "218 Total" at 143.779,55.496 h1.52
  text ".Layer_Name" at 14.656,-21.806 h1.52
M17 Embedded Cavity:
  text ".Layer_Name" at 14.656,-21.806 h1.52
M18 Embedded Assembly:
  text ".Layer_Name" at 14.656,-21.806 h1.52
M19 Embedded Keepout:
  text ".Layer_Name" at 14.656,-21.806 h1.52

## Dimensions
0,-10.16 to 25.4,-10.16 on M2 Board Dimensions
0,0 to 0,70 on M2 Board Dimensions
0,0 to 106.25,0 on M2 Board Dimensions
